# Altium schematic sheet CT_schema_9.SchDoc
size 274 x 160 mm
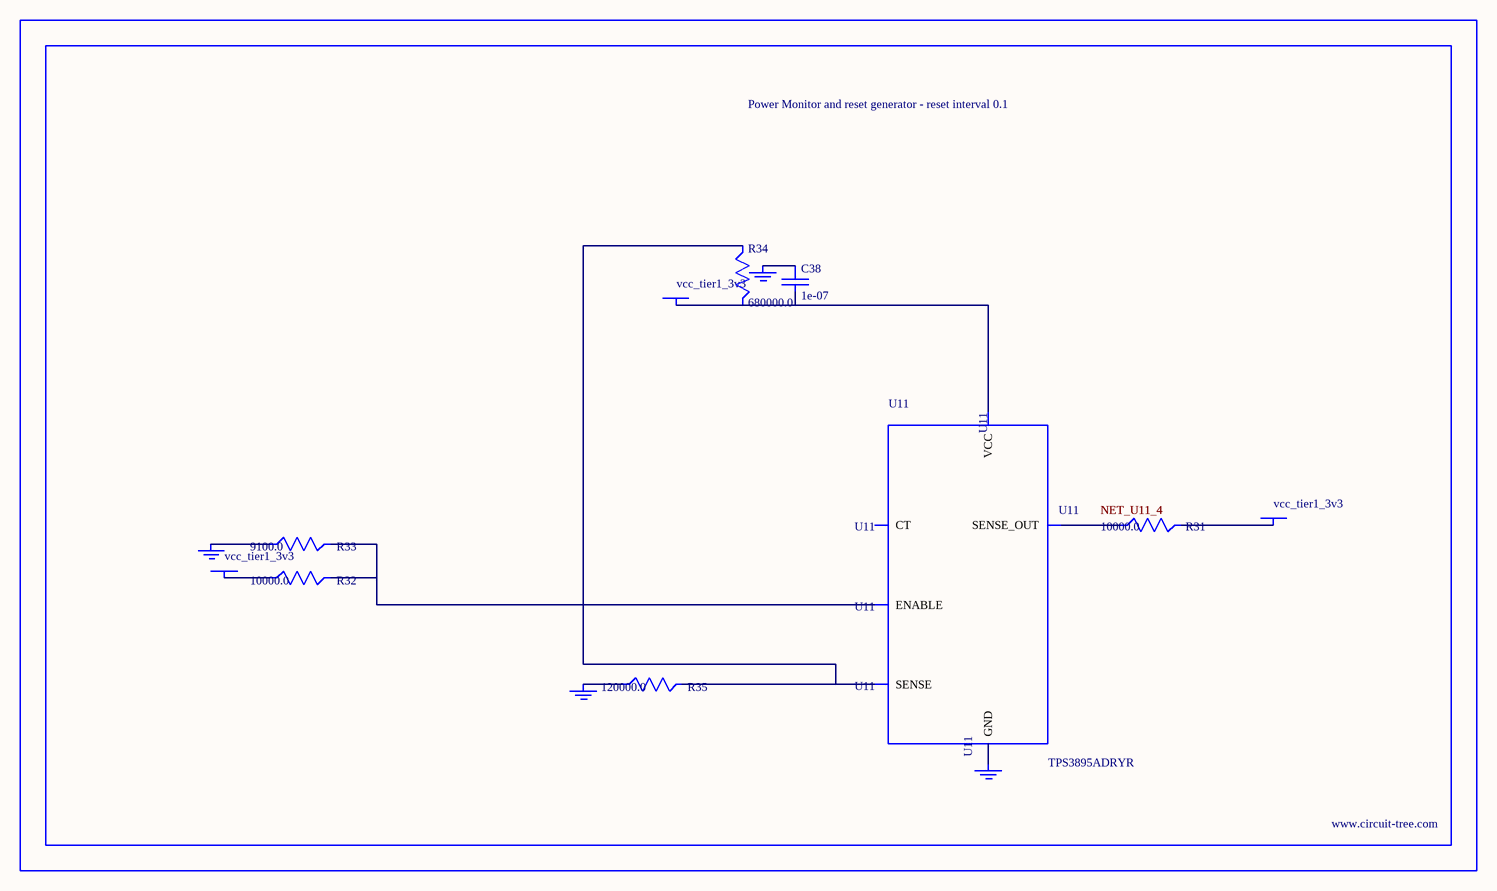
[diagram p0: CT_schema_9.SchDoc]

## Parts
BORDER8  (no value)
C38  1e-07  [C0402]
GND_INSTANCE_8_0  (no value)
GND_INSTANCE_8_1  (no value)
GND_INSTANCE_8_2  (no value)
GND_INSTANCE_8_3  (no value)
POWER_INSTANCE_8_0  vcc_tier1_3v3
POWER_INSTANCE_8_1  vcc_tier1_3v3
POWER_INSTANCE_8_2  vcc_tier1_3v3
R31  10000.0  [R0603]
R32  10000.0  [R0603]
R33  9100.0  [R0603]
R34  680000.0  [R0603]
R35  120000.0  [R0603]
U11  TPS3895ADRYR  [SON-6]

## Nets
NetC38_1: C38.1 GND_INSTANCE_8_2.0(GND)
NetC38_2: C38.2 POWER_INSTANCE_8_2.0(PWR) R34.2 U11.6(VCC)
NetGND_INSTANCE_8_0_0: GND_INSTANCE_8_0.0(GND) R33.1
NetGND_INSTANCE_8_1_0: GND_INSTANCE_8_1.0(GND) R35.1
NetGND_INSTANCE_8_3_0: GND_INSTANCE_8_3.0(GND) U11.2(GND)
NetPOWER_INSTANCE_8_0_0: POWER_INSTANCE_8_0.0(PWR) R32.1
NetPOWER_INSTANCE_8_1_0: POWER_INSTANCE_8_1.0(PWR) R31.2
NetR31_1: R31.1 U11.4(SENSE_OUT)
NetR32_2: R32.2 R33.2 U11.1(ENABLE)
NetR34_1: R34.1 R35.2 U11.3(SENSE)

Not connected (* = marked no-connect by the designer): U11 5(CT)

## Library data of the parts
BORDER8 = BORDER_PAGE8
C38 = C0402C104K3RACTU
GND_INSTANCE_8_0-GND_INSTANCE_8_3 = GND
POWER_INSTANCE_8_0-POWER_INSTANCE_8_2 = PWR
R31 R32 = RC0603JR-0710KL
R33 = RC0603JR-079K1L
R34 = RC0603JR-07680KL
R35 = RC0603JR-07120KL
